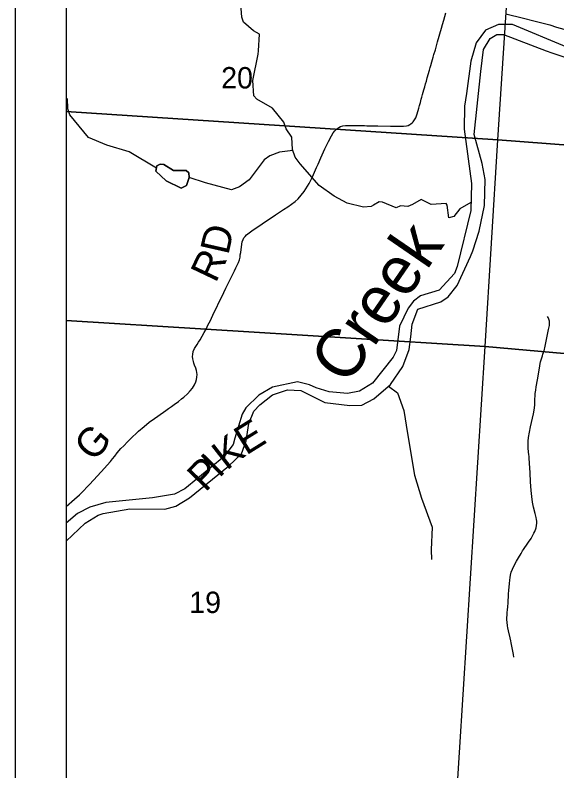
# Model space of a CAD drawing. Extents: x 0 to 34, y 0 to 22.
# Drawn here: x 2 to 3.059, y 16.271 to 17.749 of the extents above; entities that cross this region are included whole.
import ezdxf

# ---------------------------------------------------------------- set-up
doc = ezdxf.new("R2010")
doc.units = 0
for name, color, linetype in [('Default', 7, 'Continuous'), ('GM_X_County_Road', 7, 'Continuous'), ('GM_X_County_Road_Text', 7, 'Continuous'), ('GM_X_Major_River', 7, 'Continuous'), ('GM_X_Major_River_Text', 7, 'Continuous'), ('GM_X_Minor_River', 7, 'Continuous'), ('GM_X_Section', 7, 'Continuous'), ('GM_X_Section_Text', 7, 'Continuous'), ('GM_X_Township_Road', 7, 'Continuous'), ('GM_X_Township_Road_Text', 7, 'Continuous'), ('SH_Data', 7, 'Continuous'), ('SH_Text', 7, 'Continuous')]:
    doc.layers.add(name, color=color, linetype=linetype)

msp = doc.modelspace()

# ---------------------------------------------------------------- linework, layer by layer
at = {"layer": 'Default'}
msp.add_lwpolyline([(2.1, 20.9), (2.1, 16.1239), (2.1721, 16.1195), (3.6368, 16.0331), (3.9292, 16.0191), (4.6644, 15.9921)], dxfattribs=at)
for points in [[(2.1, 17.973), (2.1, 17.5604), (2.9438, 17.505), (2.9705, 17.9146)], [(2.1, 17.5604), (2.1, 17.1515), (2.9191, 17.1007), (2.9438, 17.505)], [(2.1, 17.1515), (2.1, 16.1254), (2.8549, 16.0795), (2.9191, 17.1007)]]:
    msp.add_lwpolyline(points, close=True, dxfattribs=at)
at = {"layer": 'GM_X_County_Road'}
msp.add_lwpolyline([(2.9595, 17.7514), (2.994, 17.7433), (3.0145, 17.738), (3.0299, 17.7343), (3.0455, 17.7298), (3.0589, 17.7258), (3.0732, 17.7216), (3.1003, 17.7139), (3.1161, 17.7094), (3.1283, 17.7061), (3.1352, 17.7041), (3.1437, 17.7021), (3.1478, 17.7012), (3.1524, 17.7005), (3.1562, 17.7002), (3.1594, 17.7001), (3.1652, 17.7), (3.1715, 17.7), (3.1745, 17.6998), (3.1775, 17.6995), (3.1809, 17.6989)], dxfattribs=at)
at = {"layer": 'GM_X_Major_River'}
for points in [[(3.079, 17.6864), (2.9728, 17.7308), (2.9455, 17.7307), (2.9198, 17.7196), (2.9017, 17.6949), (2.8912, 17.6592), (2.8826, 17.5961), (2.8789, 17.5711), (2.8783, 17.5259), (2.8922, 17.4194), (2.8913, 17.367), (2.8643, 17.2572), (2.859, 17.2439), (2.8292, 17.2108), (2.7929, 17.1997), (2.7793, 17.1894), (2.7687, 17.1757), (2.7514, 17.1407), (2.7458, 17.0929), (2.7394, 17.0799), (2.699, 17.0289), (2.6733, 17.0133), (2.6498, 17.009), (2.6142, 17.0123), (2.5888, 17.0202), (2.5759, 17.0258), (2.552, 17.0314), (2.5032, 17.0214), (2.4763, 17.0057), (2.4514, 16.9806), (2.4439, 16.9684), (2.43, 16.9217), (2.4262, 16.9091), (2.4081, 16.8852), (2.3318, 16.8223), (2.3114, 16.8119), (2.2689, 16.805), (2.1777, 16.7959), (2.1463, 16.7863), (2.1217, 16.7744), (2.1, 16.7555)], [(2.9161, 17.682), (2.9289, 17.7033), (2.9422, 17.711), (2.9551, 17.711), (3.0385, 17.6791), (3.0499, 17.6753), (3.1754, 17.6329)], [(2.1, 16.7202), (2.1369, 16.7555), (2.1622, 16.7708), (2.1721, 16.7742), (2.2243, 16.7835), (2.2929, 16.7823), (2.3144, 16.7884), (2.3409, 16.8049), (2.4176, 16.8666), (2.443, 16.891), (2.4516, 16.9161), (2.4568, 16.9499), (2.4666, 16.9742), (2.4783, 16.9867), (2.5036, 17.0062), (2.5328, 17.0158), (2.5585, 17.0147), (2.6056, 16.9914), (2.6544, 16.9855), (2.6779, 16.986), (2.7014, 16.9982), (2.7339, 17.0264), (2.7584, 17.0614), (2.7704, 17.0948), (2.7738, 17.1199), (2.7767, 17.1442), (2.7873, 17.1738), (2.8323, 17.1884), (2.847, 17.1983), (2.8648, 17.2204), (2.8908, 17.2767), (2.8953, 17.2877), (2.9073, 17.3264), (2.9181, 17.3769), (2.9191, 17.4274), (2.9137, 17.4589), (2.8977, 17.5158), (2.9106, 17.6388), (2.9161, 17.682)]]:
    msp.add_lwpolyline(points, dxfattribs=at)
at = {"layer": 'GM_X_Minor_River'}
for points in [[(2.8913, 17.3824), (2.8699, 17.3703), (2.8581, 17.3554), (2.8479, 17.3524), (2.8452, 17.3771), (2.8433, 17.3805), (2.8138, 17.3786), (2.7944, 17.3881), (2.777, 17.3785), (2.7679, 17.3747), (2.7539, 17.3759), (2.7452, 17.372), (2.7186, 17.383), (2.7118, 17.3838), (2.7008, 17.3773), (2.6963, 17.375), (2.6811, 17.3735), (2.6493, 17.3811), (2.6242, 17.3947), (2.5947, 17.4156), (2.5575, 17.4585), (2.5477, 17.4714), (2.5424, 17.4859), (2.5409, 17.5102), (2.5299, 17.5269), (2.5257, 17.5398), (2.5034, 17.5668), (2.4727, 17.5846), (2.4666, 17.5911), (2.4651, 17.6215), (2.475, 17.6729), (2.4761, 17.6793), (2.4777, 17.712), (2.4663, 17.7181), (2.4466, 17.7356), (2.4432, 17.7451), (2.4402, 17.7876)], [(2.2766, 17.45), (2.2232, 17.4817), (2.1796, 17.495), (2.1433, 17.5097), (2.1069, 17.5538), (2.1031, 17.566), (2.1027, 17.5861)], [(2.543, 17.4842), (2.517, 17.4809), (2.498, 17.474), (2.487, 17.4657), (2.4578, 17.4268), (2.4389, 17.4131), (2.423, 17.4074), (2.3726, 17.421), (2.3407, 17.4313)], [(2.3407, 17.4313), (2.3354, 17.4157), (2.3248, 17.4107), (2.2956, 17.4251), (2.2755, 17.4441), (2.2774, 17.4544), (2.2835, 17.4578), (2.2907, 17.4567), (2.3096, 17.4449), (2.3347, 17.445), (2.3396, 17.4408), (2.3407, 17.4313)], [(2.2774, 17.4544), (2.2755, 17.4441), (2.2956, 17.4251), (2.3248, 17.4107), (2.3354, 17.4157), (2.3407, 17.4313)], [(2.3407, 17.4313), (2.3396, 17.4408), (2.3347, 17.445), (2.3096, 17.4449), (2.2907, 17.4567), (2.2835, 17.4578), (2.2774, 17.4544)], [(2.7303, 17.0235), (2.7477, 17.0101), (2.7602, 16.9755), (2.7674, 16.9307), (2.7813, 16.8489), (2.795, 16.8041), (2.8158, 16.7474), (2.8135, 16.7033), (2.8143, 16.6839)]]:
    msp.add_lwpolyline(points, dxfattribs=at)
at = {"layer": 'GM_X_Section'}
for points in [[(4.01, 17.8394), (3.9833, 17.4262), (2.9438, 17.505), (2.9705, 17.9146)], [(2.9438, 17.505), (3.9833, 17.4262), (3.9555, 17.0086), (2.9191, 17.1007)], [(2.9191, 17.1007), (3.9555, 17.0086), (3.8924, 16.0203), (2.8549, 16.0795)]]:
    msp.add_lwpolyline(points, close=True, dxfattribs=at)
at = {"layer": 'GM_X_Township_Road'}
for points in [[(2.4481, 17.3141), (2.4497, 17.3163), (2.4528, 17.3193), (2.4631, 17.3273), (2.4832, 17.3409), (2.509, 17.3582), (2.5249, 17.369), (2.5333, 17.3743), (2.5406, 17.379), (2.5475, 17.3843), (2.5533, 17.3897), (2.5596, 17.3966), (2.5653, 17.404), (2.5688, 17.4091), (2.575, 17.4198), (2.5791, 17.4276), (2.5815, 17.4326), (2.5875, 17.4462), (2.5895, 17.4508), (2.5925, 17.4576), (2.5981, 17.4701), (2.6032, 17.4814), (2.606, 17.4876), (2.6129, 17.5021), (2.6187, 17.5131), (2.6222, 17.5189), (2.6253, 17.5228), (2.6293, 17.5267), (2.6328, 17.5293), (2.6361, 17.5309), (2.6409, 17.5323), (2.6464, 17.533), (2.6557, 17.5333), (2.67, 17.533), (2.6756, 17.5329), (2.683, 17.5329), (2.688, 17.5328), (2.6892, 17.5328), (2.6923, 17.5327), (2.6966, 17.5326), (2.7096, 17.5322), (2.7339, 17.5317), (2.7474, 17.5316), (2.7598, 17.5317), (2.7653, 17.5325), (2.7688, 17.5335), (2.7721, 17.5351), (2.7741, 17.5365), (2.7765, 17.5383), (2.7787, 17.5405), (2.7812, 17.5441), (2.7834, 17.5485), (2.7863, 17.556), (2.7897, 17.5674), (2.791, 17.5721), (2.7926, 17.5781), (2.7944, 17.5847), (2.7956, 17.5889), (2.7969, 17.5937), (2.7994, 17.6027), (2.8011, 17.6086), (2.8028, 17.6146), (2.8042, 17.62), (2.8061, 17.6266), (2.8102, 17.6415), (2.8118, 17.6469), (2.8127, 17.6505), (2.8149, 17.6576), (2.8175, 17.6666), (2.819, 17.6719), (2.8218, 17.6815), (2.824, 17.689), (2.8263, 17.697), (2.8338, 17.7233), (2.836, 17.731), (2.8385, 17.7393), (2.8424, 17.7536)], [(2.1, 16.7881), (2.1164, 16.8022), (2.1256, 16.8105), (2.1302, 16.8151), (2.1344, 16.8193), (2.1405, 16.8257), (2.1456, 16.8309), (2.153, 16.8391), (2.1682, 16.8558), (2.1864, 16.8761), (2.1904, 16.8811), (2.1947, 16.8862), (2.1998, 16.8925), (2.207, 16.901), (2.2125, 16.9068), (2.2198, 16.9145), (2.2291, 16.9236), (2.2372, 16.9313), (2.2414, 16.9351), (2.2521, 16.9444), (2.2624, 16.9525), (2.2724, 16.9598), (2.2901, 16.9725), (2.2947, 16.9759), (2.3001, 16.9798), (2.3057, 16.9836), (2.3111, 16.9874), (2.3194, 16.9933), (2.3255, 16.9982), (2.3301, 17.0017), (2.337, 17.008), (2.3425, 17.0139), (2.3466, 17.0194), (2.3505, 17.0258), (2.3531, 17.0314), (2.3546, 17.0361), (2.3555, 17.041), (2.3557, 17.0459), (2.3554, 17.0502), (2.3547, 17.0538), (2.3532, 17.0585), (2.351, 17.0643), (2.3496, 17.0685), (2.3487, 17.0714), (2.3476, 17.0769), (2.3472, 17.0812), (2.3474, 17.0855), (2.3485, 17.091), (2.3509, 17.0967), (2.3558, 17.1047), (2.3589, 17.1095), (2.3618, 17.1141), (2.3659, 17.1213), (2.3697, 17.1281), (2.3741, 17.1363), (2.3772, 17.1424), (2.3818, 17.1519), (2.3889, 17.1664), (2.3943, 17.1776), (2.398, 17.1854), (2.4024, 17.1943), (2.408, 17.2062), (2.4123, 17.2151), (2.4179, 17.2268), (2.4209, 17.233), (2.4237, 17.2385), (2.429, 17.2491), (2.4317, 17.2545), (2.4338, 17.2585), (2.4367, 17.2653), (2.4385, 17.2705), (2.4398, 17.2759), (2.4404, 17.2802), (2.4411, 17.2845), (2.4425, 17.2961), (2.4443, 17.3053), (2.4459, 17.31), (2.4475, 17.3133), (2.4481, 17.3141)], [(2.9755, 16.4928), (2.9746, 16.4984), (2.9728, 16.5079), (2.971, 16.5176), (2.9703, 16.5209), (2.9693, 16.5252), (2.9679, 16.5308), (2.9647, 16.5446), (2.9635, 16.5504), (2.9627, 16.5544), (2.962, 16.5618), (2.9619, 16.5659), (2.9619, 16.5699), (2.9623, 16.5759), (2.9626, 16.5804), (2.9631, 16.5859), (2.9637, 16.5916), (2.9642, 16.5996), (2.9645, 16.6043), (2.9649, 16.6102), (2.9652, 16.6164), (2.9657, 16.6243), (2.9661, 16.63), (2.9667, 16.6371), (2.9672, 16.6436), (2.9681, 16.6491), (2.9688, 16.6534), (2.9702, 16.6595), (2.9724, 16.6653), (2.9759, 16.6725), (2.9806, 16.6808), (2.9846, 16.6876), (2.9894, 16.6957), (2.9925, 16.701), (2.9945, 16.704), (2.9969, 16.7077), (3.0001, 16.7123), (3.0041, 16.7179), (3.0089, 16.7251), (3.0126, 16.7316), (3.0145, 16.7355), (3.0161, 16.7388), (3.0187, 16.7458), (3.0199, 16.7506), (3.0204, 16.7549), (3.0201, 16.7592), (3.0195, 16.7626), (3.0188, 16.7663), (3.017, 16.7739), (3.0139, 16.7865), (3.0119, 16.7966), (3.0103, 16.8073), (3.0093, 16.819), (3.008, 16.8364), (3.0071, 16.8537), (3.006, 16.8726), (3.0054, 16.8826), (3.0051, 16.8861), (3.0048, 16.8889), (3.0036, 16.9014), (3.0032, 16.9092), (3.0034, 16.9154), (3.0042, 16.9228), (3.0057, 16.933), (3.008, 16.9437), (3.0099, 16.9524), (3.0139, 16.9692), (3.016, 16.9802), (3.0165, 16.9876), (3.0166, 16.9934), (3.0167, 16.9985), (3.0168, 17.0035), (3.017, 17.0061), (3.0173, 17.009), (3.0177, 17.012), (3.0183, 17.0157), (3.0192, 17.0219), (3.0216, 17.0354), (3.0252, 17.0587), (3.026, 17.0633), (3.0269, 17.0679), (3.0276, 17.0709), (3.0286, 17.0745), (3.0298, 17.0785), (3.0312, 17.0827), (3.0322, 17.0857), (3.0344, 17.0926), (3.0369, 17.1014), (3.0375, 17.1048), (3.038, 17.1081), (3.0433, 17.134), (3.0449, 17.1419), (3.0452, 17.1462), (3.0449, 17.1502), (3.0439, 17.1541), (3.0426, 17.1574), (3.0413, 17.1597)]]:
    msp.add_lwpolyline(points, dxfattribs=at)
at = {"layer": 'SH_Data'}
for p, q in [((2, 21), (2, 14)), ((2.1, 20.9), (2.1, 14.1))]:
    msp.add_line(p, q, dxfattribs=at)
at = {"layer": 'SH_Text'}
msp.add_lwpolyline([(2.1, 20.9), (2.1, 14.1), (8.0885, 14.1)], dxfattribs=at)

# ---------------------------------------------------------------- texts
at = {"layer": 'GM_X_County_Road_Text'}
for s, rotation, p in [('E', 31.8623, (2.4517, 16.8871)), ('K', 37.9256, (2.4136, 16.8572)), ('I', 45.5547, (2.3988, 16.8419)), ('P', 46.0248, (2.3722, 16.8144))]:
    msp.add_text(s, height=0.0568, rotation=rotation, dxfattribs=at).set_placement(p)
at = {"layer": 'GM_X_Major_River_Text'}
msp.add_text('Creek', height=0.0947, rotation=55.5148, dxfattribs=at).set_placement((2.6493, 17.0221))
at = {"layer": 'GM_X_Section_Text'}
for s, p in [('20', (2.4029, 17.6056)), ('19', (2.3404, 16.5794))]:
    msp.add_text(s, height=0.04186, rotation=0, dxfattribs=at).set_placement(p)
at = {"layer": 'GM_X_Township_Road_Text'}
for s, rotation, p in [('D', 77.2345, (2.4168, 17.2784)), ('R', 64.56, (2.3923, 17.2235)), ('G', 49.4537, (2.1539, 16.8734))]:
    msp.add_text(s, height=0.0568, rotation=rotation, dxfattribs=at).set_placement(p)

doc.saveas('drawing.dxf')
